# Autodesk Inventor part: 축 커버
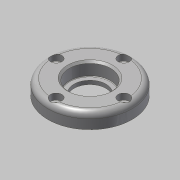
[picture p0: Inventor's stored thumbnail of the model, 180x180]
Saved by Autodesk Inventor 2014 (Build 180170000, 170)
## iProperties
Created: 2015-10
Part Number: 축 커버
Document SubType Name: Modeling
Designer: mdu
Density: 7.86 g/cm^3
Material: 강철, 연강
Mass: 76.1259 g
Surface Area: 48.0703 cm^2
Volume: 9.68523 cm^3
Appearance: 강철
Author: mdu
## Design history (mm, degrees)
sketch "스케치1"
  geometry: C1 r 22.355 at (0, 0) reference; C2 r 14 at (0, 0) reference; C3 r 1.23 at (0, 18) reference; 1 further point
extrude "돌출1" new body sketch "스케치1" distance "d0" = 8; taper "d1" = 0 deg
sketch "스케치2"
  geometry: C1 r 14 at (0, 0) reference; 1 further point
extrude "돌출2" join sketch "스케치2" distance "d2" = 3; taper "d3" = 0 deg
hole "구멍1" diameter "d6" = 17; stored, may be unused: countersink angle "d10" = 90 deg, drill point angle "d12" = 118 deg; dims "d4" = 10, "d5" = 10, "d7" = 6, "d8" = 23, "d9" = 2, "d11" = 8
hole "구멍2" diameter "d15" = 22; stored, may be unused: countersink angle "d19" = 90 deg, drill point angle "d21" = 0 deg; dims "d13" = 10, "d14" = 10, "d16" = 6, "d17" = 25, "d18" = 2, "d20" = 7
fillet "모깎기1" dims "d22" = 3, "d23" = 0.3
chamfer "모따기1" distance "d24" = 1; stored, may be unused: second distance "d25" = 2, angle "d26" = 45 deg
sketch "스케치3"
  geometry: 2 further points
hole "구멍3" sketch "스케치3" at (0, 18) diameter "d27" = 3.4; stored, may be unused: countersink angle "d31" = 90 deg, drill point angle "d33" = 118 deg; dims "d28" = 6, "d29" = 6, "d30" = 3.3, "d32" = 7
node "솔리드1"
pattern_circular "원형 패턴1" dims angle "d35" = 360 deg
node "참조1"
node "참조2"
node "참조3"
